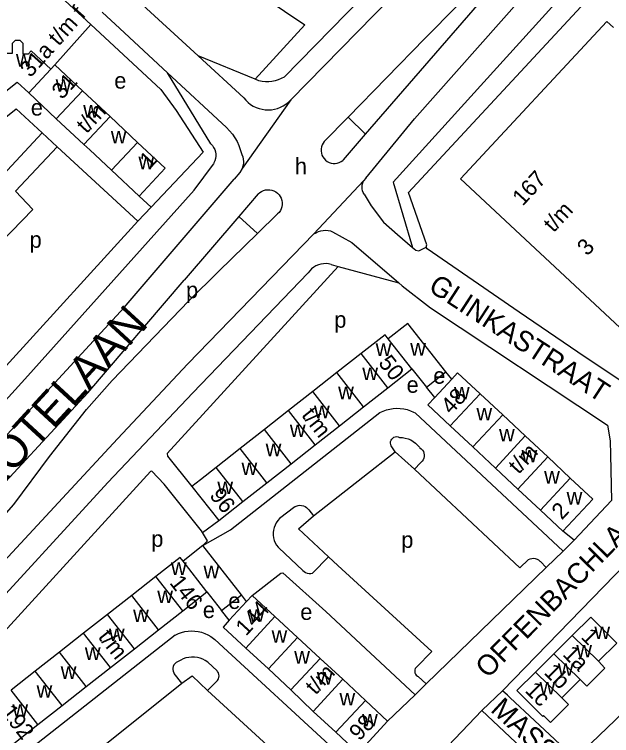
# Model space of a CAD drawing. Extents: x 159045 to 160918, y 380454 to 382516.
# Drawn here: x 159786.4 to 159933.2, y 381769.4 to 381946.6 of the extents above; entities that cross this region are included whole.
import ezdxf

# ---------------------------------------------------------------- set-up
doc = ezdxf.new("R2010")
doc.units = 0
for name, color, linetype in [('BLT_Basislijn', 7, 'Continuous'), ('BLT_Bebouwing', 7, 'Continuous'), ('BLT_Centroide', 7, 'Continuous'), ('BLT_Huisnummer', 7, 'Continuous'), ('BLT_Huisnummer_ tussenligend', 7, 'Continuous'), ('BLT_Huisnummer_reeks', 7, 'Continuous'), ('BLT_Huisnummer_zonder_bebouwing', 7, 'Continuous'), ('BLT_Onderverdeling_panden', 7, 'Continuous'), ('BLT_Plantopo', 7, 'Continuous'), ('BLT_Straatnaam', 7, 'Continuous'), ('BLT_Straatnaam_hoofdweg', 7, 'Continuous'), ('BLT_Vlakafsluiter', 7, 'Continuous')]:
    doc.layers.add(name, color=color, linetype=linetype)

msp = doc.modelspace()

# ---------------------------------------------------------------- linework, layer by layer
at = {"layer": 'BLT_Basislijn'}
for p, q in [((159798.65, 381984.11), (159857.75, 381944)), ((159852.67, 381931.16), (159896.87, 381976.27)), ((159854.31, 381925.54), (159900.45, 381972.78)), ((159831.58, 381936.34), (159799.32, 381965.97)), ((159872.71, 381917.13), (159906.74, 381956.42)), ((159930.77, 381954.07), (159883.27, 381902.84)), ((159884.74, 381920.9), (159913.54, 381953.4)), ((159812.3, 381943.06), (159807.92, 381947.11)), ((159805.18, 381944.06), (159796.32, 381934.15)), ((159823.99, 381932.23), (159812.3, 381943.06)), ((159857.75, 381944), (159845.56, 381930.61)), ((159842.77, 381926.06), (159831.58, 381936.34)), ((159845.56, 381930.61), (159831.58, 381936.34)), ((159838.54, 381918.77), (159823.99, 381932.23)), ((159834.67, 381914.75), (159823.99, 381932.23)), ((159846.48, 381930.23), (159845.56, 381930.61)), ((159862.55, 381915.35), (159868.39, 381921.31)), ((159868.39, 381921.31), (159872.71, 381917.13)), ((159872.8, 381906.34), (159884.74, 381920.9)), ((159867.26, 381910.84), (159872.71, 381917.13)), ((159796.88, 381914.05), (159816.73, 381895.72)), ((159841.57, 381914.38), (159842.31, 381912.1)), ((159819.99, 381899.17), (159832.74, 381912.7)), ((159830.57, 381903.39), (159835.29, 381909.8)), ((159842.37, 381908.71), (159841.77, 381907.69)), ((159841.77, 381907.69), (159840.39, 381906.09)), ((159872.8, 381906.34), (159872.18, 381905.67)), ((159821.41, 381893.17), (159830.57, 381903.39)), ((159819.99, 381899.17), (159817.05, 381901.91)), ((159846.32, 381902.45), (159841.58, 381896.93)), ((159816.73, 381895.72), (159819.99, 381899.17)), ((159841.58, 381896.93), (159828.09, 381881.26)), ((159841.58, 381896.93), (159846.15, 381892.72)), ((159846.15, 381892.72), (159851.09, 381897.53)), ((159788.98, 381856.91), (159821.41, 381893.17)), ((159836.63, 381883.45), (159846.15, 381892.72)), ((159864.25, 381885.13), (159865.93, 381884.66)), ((159865.93, 381884.66), (159880.9, 381880.57)), ((159893.87, 381856.93), (159892.41, 381858.72)), ((159889.71, 381852.46), (159887.65, 381854.98)), ((159884.87, 381848.66), (159921.25, 381814.72)), ((159932.83, 381841.78), (159932.9, 381838.39)), ((159879.97, 381839.12), (159879.01, 381840.59)), ((159872, 381832.87), (159879.97, 381839.12)), ((159879.97, 381839.12), (159884.74, 381834.85)), ((159886.17, 381836.39), (159884.74, 381834.85)), ((159859.89, 381823.37), (159872, 381832.87)), ((159855.27, 381825.54), (159851.55, 381822.69)), ((159858.76, 381824.82), (159859.89, 381823.37)), ((159832.6, 381819.29), (159836.59, 381822.18)), ((159923.98, 381817.37), (159921.21, 381819.61)), ((159921.25, 381814.72), (159923.98, 381817.37)), ((159851.34, 381815.49), (159857.29, 381809.95)), ((159917.09, 381810.69), (159921.25, 381814.72)), ((159859.68, 381809.29), (159863.6, 381813.28)), ((159863.6, 381813.28), (159865.87, 381811.19)), ((159915.69, 381812.11), (159917.09, 381810.69)), ((159887.61, 381782.05), (159917.09, 381810.69)), ((159843.47, 381802.31), (159842.22, 381803.93)), ((159839.21, 381797.7), (159837.31, 381800.09)), ((159835.62, 381792.99), (159868.69, 381762.63)), ((159833.9, 381787.42), (159836.18, 381785.29)), ((159827.56, 381782.29), (159825.69, 381784.67)), ((159885.61, 381783.88), (159887.61, 381782.05)), ((159820.07, 381776.29), (159827.56, 381782.29)), ((159833.81, 381780.42), (159836.09, 381782.65)), ((159884.88, 381779.4), (159887.61, 381782.05)), ((159878.1, 381772.95), (159884.88, 381779.4)), ((159807.46, 381766.18), (159820.07, 381776.29)), ((159901.27, 381775.55), (159876.77, 381750)), ((159917.63, 381760.24), (159901.27, 381775.55))]:
    msp.add_line(p, q, dxfattribs=at)
for points in [[(159938.36, 381970.36), (159879.48, 381905.36), (159884.22, 381889.32)], [(159790.35, 381957.82), (159805.18, 381944.06)], [(159868.39, 381921.31), (159887.26, 381940.6), (159895.32, 381948.77)], [(159805.18, 381944.06), (159822.35, 381928.13), (159826.12, 381922.94), (159832.74, 381912.7)], [(159852.67, 381931.16), (159851.97, 381930.77), (159851.23, 381930.46), (159850.47, 381930.23), (159849.68, 381930.07), (159848.89, 381929.99), (159848.09, 381929.99), (159847.29, 381930.07), (159846.48, 381930.23)], [(159842.77, 381926.06), (159843.27, 381925.47), (159843.83, 381924.93), (159844.43, 381924.45), (159845.09, 381924.04), (159845.78, 381923.7), (159846.51, 381923.43), (159847.26, 381923.24), (159848.02, 381923.13), (159848.79, 381923.1), (159849.56, 381923.15), (159850.33, 381923.27), (159851.07, 381923.48), (159851.79, 381923.76), (159852.48, 381924.11), (159853.12, 381924.53), (159853.73, 381925.02), (159854.31, 381925.54)], [(159741.44, 381886.87), (159786.79, 381923.36), (159793.21, 381917.44)], [(159838.54, 381918.77), (159839.28, 381917.98), (159839.95, 381917.14), (159840.57, 381916.25), (159841.11, 381915.32), (159841.57, 381914.38)], [(159793.21, 381917.44), (159782.4, 381905.92), (159771.73, 381894.65), (159775.99, 381890.48), (159764.73, 381878.39)], [(159793.21, 381917.44), (159796.88, 381914.05)], [(159796.88, 381914.05), (159786.67, 381903.16), (159790.93, 381898.65), (159780.26, 381887.73), (159768.4, 381875)], [(159834.67, 381914.75), (159835.05, 381914.33), (159835.36, 381913.86), (159835.61, 381913.35), (159835.77, 381912.81), (159835.87, 381912.26), (159835.88, 381911.69), (159835.81, 381911.13), (159835.67, 381910.59), (159835.44, 381910.07), (159835.29, 381909.8)], [(159862.55, 381915.35), (159862.25, 381914.93), (159862.01, 381914.48), (159861.85, 381914), (159861.76, 381913.5), (159861.75, 381912.99), (159861.83, 381912.48), (159861.98, 381911.99), (159862.2, 381911.53), (159862.5, 381911.12), (159862.85, 381910.75), (159863.26, 381910.44), (159863.71, 381910.21), (159864.2, 381910.04), (159864.7, 381909.95), (159865.21, 381909.94), (159865.71, 381910.01), (159866.2, 381910.16), (159866.66, 381910.39), (159867.08, 381910.68), (159867.26, 381910.84)], [(159842.31, 381912.1), (159842.51, 381911.56), (159842.64, 381910.99), (159842.69, 381910.42), (159842.67, 381909.84), (159842.56, 381909.26), (159842.37, 381908.71)], [(159794.4, 381853.97), (159813.34, 381874.56), (159840.39, 381906.09)], [(159872.38, 381902.36), (159872.13, 381902.79), (159871.95, 381903.24), (159871.85, 381903.73), (159871.83, 381904.22), (159871.88, 381904.71), (159872.02, 381905.18), (159872.18, 381905.67)], [(159846.32, 381902.45), (159846.71, 381902.8), (159847.15, 381903.08), (159847.63, 381903.3), (159848.13, 381903.43), (159848.65, 381903.49), (159849.18, 381903.48), (159849.69, 381903.38), (159850.18, 381903.2), (159850.64, 381902.96), (159851.06, 381902.64), (159851.43, 381902.26), (159851.73, 381901.84), (159851.96, 381901.37), (159852.12, 381900.87), (159852.21, 381900.36), (159852.21, 381899.83), (159852.13, 381899.32), (159851.98, 381898.82), (159851.75, 381898.35), (159851.45, 381897.92), (159851.09, 381897.53)], [(159872.38, 381902.36), (159874.03, 381899.49), (159877.07, 381895.49), (159880.52, 381892.47), (159884.22, 381889.32)], [(159887.57, 381889.38), (159887.78, 381889.94), (159883.27, 381902.84)], [(159784.38, 381860.25), (159816.73, 381895.72)], [(159860.01, 381892.63), (159860.56, 381892.92), (159861.1, 381893.19), (159861.68, 381893.38), (159862.27, 381893.49), (159862.87, 381893.52), (159863.47, 381893.47), (159864.06, 381893.35), (159864.58, 381893.16)], [(159864.58, 381893.16), (159869.35, 381890.54), (159880.9, 381880.57)], [(159860.01, 381892.63), (159829.01, 381860.67), (159811.69, 381842.26), (159798.24, 381827.72)], [(159884.22, 381889.32), (159885.02, 381888.64), (159885.78, 381888.47), (159887.57, 381889.38)], [(159910.44, 381873.44), (159887.81, 381888.95), (159887.57, 381889.38)], [(159865.93, 381884.66), (159823.95, 381838.68), (159823.99, 381837.99), (159830.01, 381830.55)], [(159864.25, 381885.13), (159863.62, 381885.26), (159862.98, 381885.32), (159862.34, 381885.29), (159861.7, 381885.19), (159861.09, 381885.01), (159860.5, 381884.75), (159859.95, 381884.42), (159859.44, 381884.03), (159858.99, 381883.57), (159858.59, 381883.07), (159858.52, 381882.96)], [(159782.63, 381822.15), (159786.21, 381826.18), (159794.99, 381837.92), (159804.12, 381849.5), (159810.38, 381856.62), (159829.29, 381876.17), (159836.63, 381883.45)], [(159858.52, 381882.96), (159830.25, 381853.55), (159809.37, 381831.59)], [(159771.01, 381817.53), (159804.44, 381853.6), (159828.09, 381881.26)], [(159880.9, 381880.57), (159881.72, 381879.87), (159888.68, 381874.45), (159932.12, 381845.68), (159932.83, 381841.78)], [(159948.66, 381860.71), (159947.44, 381859.65), (159941.62, 381854.9), (159938.73, 381854.35), (159924.83, 381863.57), (159910.44, 381873.44)], [(159712.2, 381773.81), (159735.79, 381799.05), (159776.92, 381843.76), (159788.98, 381856.91)], [(159719, 381772.11), (159749.25, 381805.09), (159794.4, 381853.97)], [(159832.72, 381816.05), (159839.5, 381819.9), (159876.24, 381848.76)], [(159876.24, 381848.76), (159877.02, 381849.12), (159877.83, 381849.4), (159878.65, 381849.61), (159879.5, 381849.74), (159880.36, 381849.79), (159881.21, 381849.76), (159882.06, 381849.65), (159882.89, 381849.46), (159883.71, 381849.2), (159884.49, 381848.85), (159884.87, 381848.66)], [(159879.01, 381840.59), (159878.88, 381840.91), (159878.83, 381841.25), (159878.85, 381841.59), (159878.96, 381841.93), (159879.13, 381842.22), (159879.37, 381842.47), (159879.66, 381842.66), (159879.99, 381842.78), (159880.33, 381842.82), (159880.68, 381842.78), (159881.06, 381842.63)], [(159881.06, 381842.63), (159881.76, 381842.59), (159882.46, 381842.47), (159883.13, 381842.27), (159883.78, 381842), (159884.4, 381841.65), (159884.97, 381841.24), (159885.49, 381840.76), (159885.96, 381840.23), (159886.07, 381840.07)], [(159886.07, 381840.07), (159886.4, 381839.82), (159886.68, 381839.5), (159886.9, 381839.14), (159887.04, 381838.74), (159887.1, 381838.33), (159887.09, 381837.91), (159886.99, 381837.5), (159886.82, 381837.11), (159886.59, 381836.77), (159886.28, 381836.47), (159886.17, 381836.39)], [(159932.9, 381838.39), (159933.13, 381827.16), (159923.98, 381817.37)], [(159832.6, 381819.29), (159832.39, 381819.64), (159823.22, 381831.13), (159820.2, 381834.34), (159819.82, 381834.26), (159774.32, 381784.48), (159774.15, 381783.98), (159779.62, 381775.9)], [(159884.74, 381834.85), (159910.62, 381810.59), (159912.72, 381812.62)], [(159809.37, 381831.59), (159776.1, 381795.36), (159761.41, 381779.42), (159734.66, 381750.65)], [(159798.24, 381827.72), (159773.47, 381801.08), (159748.42, 381774.17), (159737.26, 381762.08)], [(159855.27, 381825.54), (159855.66, 381825.75), (159856.09, 381825.89), (159856.53, 381825.96), (159856.98, 381825.94), (159857.41, 381825.84), (159857.83, 381825.67), (159858.2, 381825.43), (159858.53, 381825.12), (159858.76, 381824.82)], [(159851.55, 381822.69), (159851.12, 381822.21), (159850.75, 381821.68), (159850.45, 381821.11), (159850.22, 381820.5), (159850.07, 381819.88), (159850, 381819.23), (159850.01, 381818.59), (159850.1, 381817.95), (159850.26, 381817.33), (159850.51, 381816.73), (159850.82, 381816.17), (159851.2, 381815.65), (159851.34, 381815.49)], [(159863.6, 381813.28), (159856.23, 381820.16), (159859.89, 381823.37)], [(159832.72, 381816.05), (159833.88, 381817.22), (159832.6, 381819.29)], [(159969.6, 381756.85), (159987.65, 381774.62), (159942.26, 381817.34), (159906.31, 381780.37)], [(159912.72, 381812.62), (159913.12, 381812.8), (159913.54, 381812.91), (159913.98, 381812.93), (159914.41, 381812.87), (159914.83, 381812.74), (159915.21, 381812.53), (159915.55, 381812.26), (159915.69, 381812.11)], [(159865.87, 381811.19), (159888.99, 381790.01), (159885.1, 381786.13)], [(159857.29, 381809.95), (159857.61, 381809.66), (159857.97, 381809.43), (159858.38, 381809.28), (159858.8, 381809.2), (159859.23, 381809.2), (159859.68, 381809.29)], [(159844.81, 381803.77), (159851.85, 381809.3), (159852.32, 381809.33), (159862.95, 381799.88), (159884.88, 381779.4)], [(159825.93, 381794.08), (159787.61, 381763.98), (159782.09, 381761.45)], [(159825.93, 381794.08), (159826.68, 381794.44), (159827.46, 381794.72), (159828.26, 381794.93), (159829.08, 381795.05), (159829.91, 381795.1), (159830.74, 381795.06), (159831.56, 381794.95), (159832.37, 381794.76), (159833.15, 381794.49), (159833.91, 381794.15), (159834.63, 381793.74), (159835.3, 381793.26), (159835.62, 381792.99)], [(159833.9, 381787.42), (159833.31, 381787.81), (159832.69, 381788.13), (159832.03, 381788.38), (159831.35, 381788.55), (159830.65, 381788.65), (159829.95, 381788.66), (159829.25, 381788.59), (159828.56, 381788.45), (159827.9, 381788.22), (159827.26, 381787.93), (159826.81, 381787.66)], [(159826.81, 381787.66), (159826.44, 381787.53), (159826.11, 381787.32), (159825.82, 381787.04), (159825.6, 381786.72), (159825.44, 381786.36), (159825.36, 381785.97), (159825.36, 381785.58), (159825.44, 381785.19), (159825.59, 381784.83), (159825.69, 381784.67)], [(159836.09, 381782.65), (159836.34, 381782.94), (159836.53, 381783.28), (159836.65, 381783.65), (159836.68, 381784.03), (159836.64, 381784.41), (159836.52, 381784.78), (159836.33, 381785.11), (159836.18, 381785.29)], [(159885.1, 381786.13), (159884.92, 381785.83), (159884.82, 381785.5), (159884.79, 381785.16), (159884.84, 381784.82), (159884.97, 381784.5), (159885.17, 381784.21), (159885.43, 381783.99), (159885.61, 381783.88)], [(159827.56, 381782.29), (159830.06, 381784.03), (159833.81, 381780.42)], [(159924.2, 381763.75), (159943.93, 381782.66), (159969.6, 381756.85)], [(159833.81, 381780.42), (159858.41, 381757.94), (159859.91, 381759.82)], [(159906.31, 381780.37), (159901.37, 381775.65), (159901.27, 381775.55)], [(159908.24, 381778.66), (159907.57, 381779.28), (159906.31, 381780.37)], [(159908.24, 381778.66), (159914.18, 381773.11), (159924.2, 381763.75)]]:
    msp.add_lwpolyline(points, dxfattribs=at)
at = {"layer": 'BLT_Bebouwing'}
for p, q in [((159796.32, 381934.15), (159795.35, 381933.11)), ((159803.11, 381927.81), (159796.32, 381934.15)), ((159789.91, 381927.28), (159796.69, 381920.94)), ((159809.9, 381921.46), (159803.11, 381927.81)), ((159816.68, 381915.12), (159809.9, 381921.46)), ((159796.69, 381920.94), (159803.48, 381914.6)), ((159823.47, 381908.78), (159816.68, 381915.12)), ((159871.58, 381863.21), (159865.64, 381858.54)), ((159878.15, 381854.84), (159884.09, 381859.5)), ((159884.09, 381859.5), (159887.65, 381854.98)), ((159865.64, 381858.54), (159859.7, 381853.88)), ((159887.65, 381854.98), (159892.41, 381858.72)), ((159893.87, 381856.93), (159889.71, 381852.46)), ((159859.7, 381853.88), (159853.76, 381849.21)), ((159872.22, 381850.17), (159878.15, 381854.84)), ((159906.41, 381848.16), (159900.87, 381853.33)), ((159866.28, 381845.51), (159872.22, 381850.17)), ((159853.76, 381849.21), (159847.83, 381844.55)), ((159911.95, 381842.99), (159906.41, 381848.16)), ((159860.34, 381840.84), (159866.28, 381845.51)), ((159893.51, 381845.44), (159899.05, 381840.28)), ((159847.83, 381844.55), (159841.89, 381839.88)), ((159917.48, 381837.83), (159911.95, 381842.99)), ((159841.89, 381839.88), (159835.95, 381835.22)), ((159854.4, 381836.18), (159860.34, 381840.84)), ((159899.05, 381840.28), (159904.59, 381835.11)), ((159923.02, 381832.66), (159917.48, 381837.83)), ((159848.46, 381831.51), (159854.4, 381836.18)), ((159904.59, 381835.11), (159910.13, 381829.94)), ((159842.52, 381826.85), (159848.46, 381831.51)), ((159830.01, 381830.55), (159836.59, 381822.18)), ((159910.13, 381829.94), (159915.67, 381824.78)), ((159836.59, 381822.18), (159842.52, 381826.85)), ((159915.67, 381824.78), (159921.21, 381819.61)), ((159832.72, 381816.05), (159827.85, 381812.23)), ((159842.22, 381803.93), (159832.72, 381816.05)), ((159821.17, 381808.47), (159815.23, 381803.81)), ((159827.78, 381800.03), (159833.71, 381804.68)), ((159833.71, 381804.68), (159837.31, 381800.09)), ((159815.23, 381803.81), (159809.3, 381799.16)), ((159837.31, 381800.09), (159842.22, 381803.93)), ((159843.47, 381802.31), (159839.21, 381797.7)), ((159844.81, 381803.77), (159843.47, 381802.31)), ((159850.38, 381798.62), (159844.81, 381803.77)), ((159809.3, 381799.16), (159803.36, 381794.51)), ((159821.84, 381795.38), (159827.78, 381800.03)), ((159855.94, 381793.48), (159850.38, 381798.62)), ((159815.9, 381790.73), (159821.84, 381795.38)), ((159803.36, 381794.51), (159797.43, 381789.86)), ((159861.51, 381788.34), (159855.94, 381793.48)), ((159918.97, 381789.47), (159923.51, 381793.99)), ((159809.97, 381786.08), (159815.9, 381790.73)), ((159843.23, 381790.88), (159848.8, 381785.74)), ((159797.43, 381789.86), (159791.49, 381785.21)), ((159867.08, 381783.2), (159861.51, 381788.34)), ((159914.44, 381784.95), (159918.97, 381789.47)), ((159791.49, 381785.21), (159785.56, 381780.55)), ((159804.04, 381781.42), (159809.97, 381786.08)), ((159848.8, 381785.74), (159854.36, 381780.6)), ((159909.91, 381780.44), (159914.44, 381784.95)), ((159872.66, 381778.02), (159867.08, 381783.2)), ((159925.45, 381783.18), (159920.91, 381778.66)), ((159798.1, 381776.77), (159804.04, 381781.42)), ((159854.36, 381780.6), (159859.79, 381775.33)), ((159878.1, 381772.95), (159872.66, 381778.02)), ((159792.17, 381772.12), (159798.1, 381776.77)), ((159859.79, 381775.33), (159865.36, 381770.18)), ((159870.85, 381765.1), (159878.1, 381772.95)), ((159786.23, 381767.47), (159792.17, 381772.12)), ((159865.36, 381770.18), (159870.85, 381765.1))]:
    msp.add_line(p, q, dxfattribs=at)
for points in [[(159795.35, 381933.11), (159790.52, 381937.61), (159789.76, 381936.8), (159788.5, 381936.8), (159788.51, 381939.45), (159787.82, 381940.14), (159786.59, 381940.14), (159785.85, 381939.41), (159785.85, 381936.93), (159784.61, 381936.93), (159783.83, 381937.91), (159778.73, 381933.85)], [(159783.85, 381927.4), (159787.06, 381929.94), (159789.91, 381927.28)], [(159803.48, 381914.6), (159804.91, 381913.26), (159810.27, 381908.26)], [(159817.05, 381901.91), (159823.47, 381908.78)], [(159810.27, 381908.26), (159817.05, 381901.91)], [(159892.41, 381858.72), (159883.05, 381870.62), (159878.26, 381866.86)], [(159878.26, 381866.86), (159877.48, 381867.85), (159871.58, 381863.21)], [(159900.87, 381853.33), (159895.33, 381858.49), (159893.87, 381856.93)], [(159889.71, 381852.46), (159887.98, 381850.61), (159893.51, 381845.44)], [(159835.95, 381835.22), (159832.14, 381832.22), (159830.01, 381830.55)], [(159921.21, 381819.61), (159928.56, 381827.49), (159923.02, 381832.66)], [(159827.85, 381812.23), (159827.13, 381813.14), (159821.17, 381808.47)], [(159839.21, 381797.7), (159837.66, 381796.03), (159843.23, 381790.88)], [(159923.51, 381793.99), (159928.04, 381798.51), (159934.42, 381792.11), (159929.98, 381787.69)], [(159929.98, 381787.69), (159931.54, 381785.93), (159927.08, 381781.48), (159925.45, 381783.18)], [(159920.91, 381778.66), (159922.61, 381777.04), (159918.14, 381772.59), (159916.45, 381774.29), (159916.24, 381774.08), (159909.91, 381780.44)]]:
    msp.add_lwpolyline(points, dxfattribs=at)
at = {"layer": 'BLT_Onderverdeling_panden'}
for p, q in [((159795.35, 381933.11), (159789.91, 381927.28)), ((159803.11, 381927.81), (159796.69, 381920.94)), ((159809.9, 381921.46), (159803.48, 381914.6)), ((159816.68, 381915.12), (159810.27, 381908.26)), ((159884.09, 381859.5), (159878.26, 381866.86)), ((159878.15, 381854.84), (159871.58, 381863.21)), ((159872.22, 381850.17), (159865.64, 381858.54)), ((159866.28, 381845.51), (159859.7, 381853.88)), ((159893.51, 381845.44), (159900.87, 381853.33)), ((159860.34, 381840.84), (159853.76, 381849.21)), ((159899.05, 381840.28), (159906.41, 381848.16)), ((159854.4, 381836.18), (159847.83, 381844.55)), ((159904.59, 381835.11), (159911.95, 381842.99)), ((159848.46, 381831.51), (159841.89, 381839.88)), ((159910.13, 381829.94), (159917.48, 381837.83)), ((159842.52, 381826.85), (159835.95, 381835.22)), ((159915.67, 381824.78), (159923.02, 381832.66)), ((159833.71, 381804.68), (159827.85, 381812.23)), ((159827.78, 381800.03), (159821.17, 381808.47)), ((159821.84, 381795.38), (159815.23, 381803.81)), ((159815.9, 381790.73), (159809.3, 381799.16)), ((159843.23, 381790.88), (159850.38, 381798.62)), ((159809.97, 381786.08), (159803.36, 381794.51)), ((159848.8, 381785.74), (159855.94, 381793.48)), ((159929.98, 381787.69), (159923.51, 381793.99)), ((159804.04, 381781.42), (159797.43, 381789.86)), ((159854.36, 381780.6), (159861.51, 381788.34)), ((159925.45, 381783.18), (159918.97, 381789.47)), ((159798.1, 381776.77), (159791.49, 381785.21)), ((159920.91, 381778.66), (159914.44, 381784.95)), ((159859.79, 381775.33), (159867.08, 381783.2)), ((159792.17, 381772.12), (159785.56, 381780.55)), ((159865.36, 381770.18), (159872.66, 381778.02))]:
    msp.add_line(p, q, dxfattribs=at)
at = {"layer": 'BLT_Plantopo'}
for p, q in [((159896.03, 381906.17), (159932.02, 381944.83)), ((159932.02, 381944.83), (159933.59, 381943.37)), ((159935.17, 381869.65), (159896.03, 381906.17))]:
    msp.add_line(p, q, dxfattribs=at)
at = {"layer": 'BLT_Vlakafsluiter'}
for p, q in [((159854.31, 381925.54), (159842.37, 381908.71)), ((159872.18, 381905.67), (159860.01, 381892.63))]:
    msp.add_line(p, q, dxfattribs=at)

# ---------------------------------------------------------------- texts
at = {"layer": 'BLT_Centroide'}
for s, p in [('w', (159786.77, 381933.72)), ('w', (159796.52, 381927.55)), ('e', (159810.93, 381928.32)), ('e', (159790.42, 381921.7)), ('w', (159803.3, 381921.2)), ('w', (159810.08, 381914.86)), ('w', (159816.88, 381908.52)), ('h', (159855.31, 381907.29)), ('p', (159790.12, 381889.22)), ('p', (159828.57, 381876.84)), ('p', (159865.01, 381869.58)), ('w', (159875.18, 381862.64)), ('w', (159883.67, 381862.72)), ('w', (159871.89, 381856.7)), ('e', (159889.34, 381855.82)), ('e', (159882.78, 381853.59)), ('w', (159865.95, 381852.02)), ('w', (159894.42, 381851.97)), ('w', (159860.02, 381847.36)), ('w', (159899.95, 381846.8)), ('w', (159854.08, 381842.7)), ('w', (159905.5, 381841.64)), ('w', (159848.14, 381838.02)), ('w', (159911.03, 381836.47)), ('w', (159842.2, 381833.36)), ('w', (159916.58, 381831.3)), ('w', (159836.27, 381828.7)), ('w', (159922.11, 381826.14)), ('p', (159820.03, 381815.74)), ('p', (159881.47, 381815.49)), ('w', (159824.86, 381808.83)), ('w', (159832.87, 381808.03)), ('w', (159821.5, 381801.92)), ('e', (159838.96, 381800.49)), ('e', (159832.7, 381798.26)), ('e', (159856.65, 381797.79)), ('w', (159815.56, 381797.27)), ('w', (159844.02, 381797.33)), ('w', (159809.62, 381792.61)), ('w', (159849.59, 381792.19)), ('w', (159928.93, 381793.09)), ('w', (159803.7, 381787.97)), ('w', (159855.16, 381787.05)), ('w', (159924.48, 381788.59)), ('w', (159797.77, 381783.31)), ('w', (159919.95, 381784.06)), ('w', (159860.72, 381781.89)), ('w', (159791.83, 381778.67)), ('w', (159915.45, 381779.5)), ('w', (159866.28, 381776.77)), ('w', (159785.89, 381774.02)), ('w', (159871.84, 381771.61))]:
    msp.add_text(s, height=4, dxfattribs=at).set_placement(p)
at = {"layer": 'BLT_Huisnummer'}
for s, p in [('1', (159925.45, 381793.42)), ('1c', (159911.68, 381780.26))]:
    msp.add_text(s, height=4, rotation=314.9058, dxfattribs=at).set_placement(p)
at = {"layer": 'BLT_Huisnummer_ tussenligend'}
for s, p in [('1a', (159920.93, 381789.14)), ('1b', (159916.34, 381784.71))]:
    msp.add_text(s, height=4, rotation=314.9058, dxfattribs=at).set_placement(p)
at = {"layer": 'BLT_Huisnummer_reeks'}
for s, rotation, p in [('31a t/m f', 48.1917, (159790.33, 381930.86)), ('31', 46.9402, (159798.08, 381925.47)), ('t/m', 46.9402, (159804.11, 381917.1)), ('1', 46.9443, (159819.67, 381908.47)), ('50', 308.1569, (159875.67, 381860.9)), ('48', 46.9881, (159893.72, 381848.08)), ('t/m', 308.1578, (159856.79, 381848.05)), ('t/m', 46.9887, (159910.29, 381833.41)), ('96', 308.1545, (159834.17, 381828.32)), ('2', 46.9881, (159920.94, 381822.2)), ('146', 308.086, (159824.35, 381806.88)), ('144', 47.2731, (159843.3, 381793.66)), ('t/m', 308.0903, (159806.78, 381793.56)), ('t/m', 47.27, (159860.42, 381779.18)), ('192', 308.0903, (159782.9, 381775.05)), ('98', 47.2691, (159871.19, 381767.89))]:
    msp.add_text(s, height=4, rotation=rotation, dxfattribs=at).set_placement(p)
at = {"layer": 'BLT_Huisnummer_zonder_bebouwing'}
for s, p in [('167', (159911.3, 381899.3)), ('t/m', (159918.91, 381892.79)), ('3', (159927.2, 381887.03))]:
    msp.add_text(s, height=4, rotation=47.1442, dxfattribs=at).set_placement(p)
at = {"layer": 'BLT_Straatnaam'}
for s, rotation, p in [('SCHUBERTLAAN', 42.1276, (159752.22, 381927.29)), ('GLINKASTRAAT', 326.9259, (159887.84, 381878.84)), ('OFFENBACHLAAN', 45.4522, (159902.76, 381783.24)), ('MASSENETSTRAAT', 317.411, (159903.18, 381775.46))]:
    msp.add_text(s, height=5, rotation=rotation, dxfattribs=at).set_placement(p)
at = {"layer": 'BLT_Straatnaam_hoofdweg'}
msp.add_text('KAREL DE GROTELAAN', height=8, rotation=47.388, dxfattribs=at).set_placement((159737.09, 381780.62))

doc.saveas('drawing.dxf')
